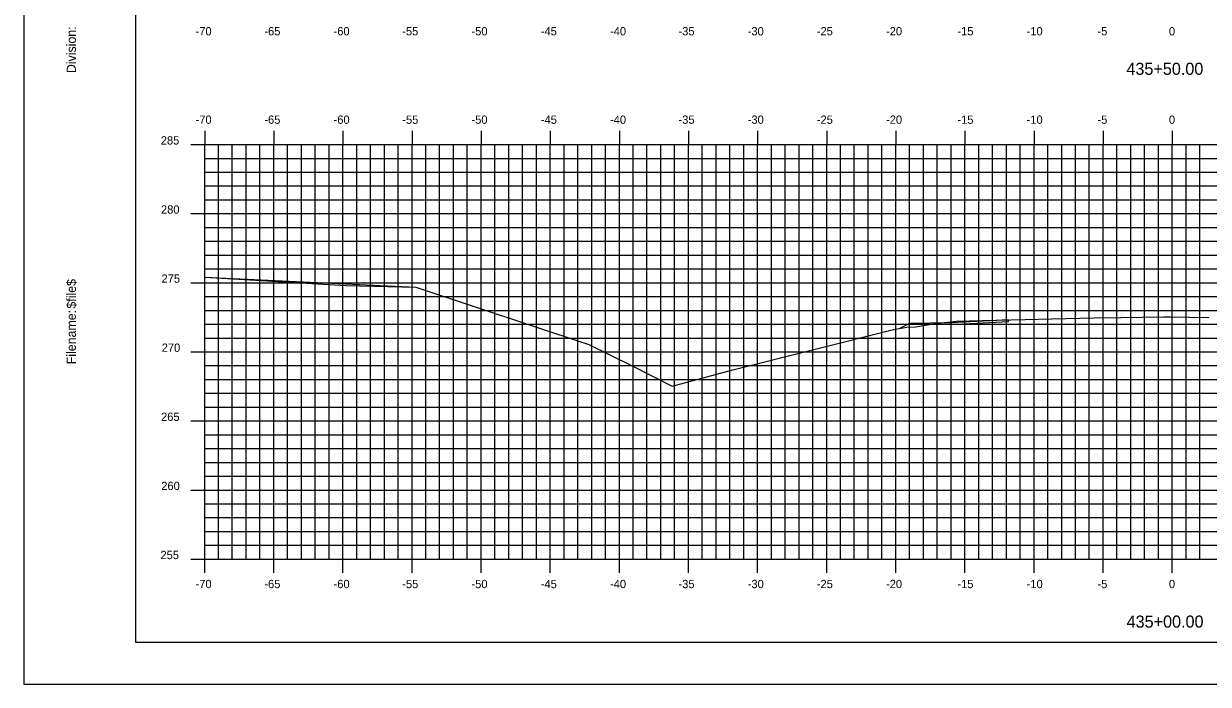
# Model space of a CAD drawing. Extents: x 1168600 to 1177589, y 610178 to 611246.
# Drawn here: x 1176654.6 to 1176740.3, y 610900.5 to 610948.3 of the extents above; entities that cross this region are included whole.
import ezdxf

# ---------------------------------------------------------------- set-up
doc = ezdxf.new("R2010")
doc.units = 0
for name, color, linetype in [('_Construction', 7, 'Continuous'), ('_Station Equation', 7, 'Continuous'), ('D_Roadway_Edge_TW', 7, 'Continuous'), ('D_Slope_Direction', 7, 'Continuous'), ('H_V ANNOTATION', 7, 'Continuous'), ('MAJOR', 7, 'Continuous'), ('MATCH LINES', 7, 'Continuous'), ('MINOR', 7, 'Continuous')]:
    doc.layers.add(name, color=color, linetype=linetype)

msp = doc.modelspace()

# ---------------------------------------------------------------- linework, layer by layer
at = {"layer": '_Construction'}
for points in [[(1176654.596, 610900.537), (1176824.596, 610900.537), (1176824.596, 611010.537), (1176654.596, 611010.537)], [(1176662.689, 610903.596), (1176822.689, 610903.596), (1176822.689, 611008.596), (1176662.689, 611008.596)]]:
    msp.add_lwpolyline(points, close=True, dxfattribs=at)
at = {"layer": '_Station Equation'}
for points in [[(1176667.689, 610929.994), (1176682.974, 610929.275), (1176695.478, 610925.138), (1176698.574, 610923.612), (1176701.51, 610922.119), (1176705.899, 610923.304), (1176717.518, 610926.22), (1176718.491, 610926.371), (1176719.109, 610926.405), (1176720.517, 610926.635), (1176721.211, 610926.723), (1176722.046, 610926.812), (1176723.965, 610926.861), (1176727.046, 610926.94), (1176728.963, 610926.98), (1176732.046, 610927.044), (1176733.961, 610927.076), (1176737.046, 610927.132), (1176737.349, 610927.134), (1176737.544, 610927.135), (1176740.331, 610927.075)], [(1176667.689, 610929.99), (1176677.908, 610929.4), (1176682.974, 610929.275), (1176695.479, 610925.138), (1176698.575, 610923.612), (1176701.51, 610922.119), (1176705.898, 610923.304), (1176717.518, 610926.22), (1176718.491, 610926.371), (1176719.109, 610926.405), (1176720.517, 610926.635), (1176721.211, 610926.723), (1176722.046, 610926.812), (1176723.966, 610926.861), (1176727.046, 610926.94), (1176728.964, 610926.98), (1176732.046, 610927.044), (1176733.962, 610927.076), (1176737.046, 610927.132), (1176737.349, 610927.134), (1176737.544, 610927.135), (1176740.33, 610927.075)]]:
    msp.add_lwpolyline(points, dxfattribs=at)
at = {"layer": 'D_Roadway_Edge_TW'}
msp.add_lwpolyline([(1176725.849, 610926.91), (1176721.69, 610926.694), (1176721.69, 610926.694), (1176721.69, 610926.569), (1176725.849, 610926.785), (1176725.849, 610926.91)], dxfattribs=at)
msp.add_lwpolyline([(1176725.849, 610926.91), (1176721.69, 610926.694), (1176721.69, 610926.694), (1176721.69, 610926.569), (1176725.849, 610926.785), (1176725.849, 610926.91)], dxfattribs=at)
at = {"layer": 'D_Slope_Direction'}
for points in [[(1176718.689, 610926.634), (1176718.016, 610926.297)], [(1176718.689, 610926.634), (1176718.016, 610926.297)], [(1176718.689, 610926.634), (1176718.016, 610926.297)], [(1176718.689, 610926.634), (1176718.016, 610926.297)], [(1176718.689, 610926.634), (1176718.016, 610926.297)], [(1176718.689, 610926.634), (1176718.016, 610926.297)], [(1176718.689, 610926.634), (1176718.016, 610926.297)], [(1176721.69, 610926.694), (1176718.689, 610926.634)], [(1176721.69, 610926.694), (1176718.689, 610926.634)]]:
    msp.add_lwpolyline(points, dxfattribs=at)
at = {"layer": 'MAJOR'}
for p, q in [((1176667.689, 610940.598), (1176667.689, 610939.596)), ((1176672.689, 610940.598), (1176672.689, 610939.596)), ((1176677.689, 610940.598), (1176677.689, 610939.596)), ((1176682.689, 610940.598), (1176682.689, 610939.596)), ((1176687.689, 610940.598), (1176687.689, 610939.596)), ((1176692.689, 610940.598), (1176692.689, 610939.596)), ((1176697.689, 610940.598), (1176697.689, 610939.596)), ((1176702.689, 610940.598), (1176702.689, 610939.596)), ((1176707.689, 610940.598), (1176707.689, 610939.596)), ((1176712.689, 610940.598), (1176712.689, 610939.596)), ((1176717.689, 610940.598), (1176717.689, 610939.596)), ((1176722.689, 610940.598), (1176722.689, 610939.596)), ((1176727.689, 610940.598), (1176727.689, 610939.596)), ((1176732.689, 610940.598), (1176732.689, 610939.596)), ((1176737.689, 610940.598), (1176737.689, 610939.596)), ((1176666.687, 610939.596), (1176667.689, 610939.596)), ((1176667.689, 610939.596), (1176807.689, 610939.596)), ((1176667.689, 610909.596), (1176667.689, 610939.596)), ((1176667.689, 610909.596), (1176667.689, 610939.596)), ((1176667.689, 610939.596), (1176807.689, 610939.596)), ((1176672.689, 610909.596), (1176672.689, 610939.596)), ((1176677.689, 610909.596), (1176677.689, 610939.596)), ((1176682.689, 610909.596), (1176682.689, 610939.596)), ((1176687.689, 610909.596), (1176687.689, 610939.596)), ((1176692.689, 610909.596), (1176692.689, 610939.596)), ((1176697.689, 610909.596), (1176697.689, 610939.596)), ((1176702.689, 610909.596), (1176702.689, 610939.596)), ((1176707.689, 610909.596), (1176707.689, 610939.596)), ((1176712.689, 610909.596), (1176712.689, 610939.596)), ((1176717.689, 610909.596), (1176717.689, 610939.596)), ((1176722.689, 610909.596), (1176722.689, 610939.596)), ((1176727.689, 610909.596), (1176727.689, 610939.596)), ((1176732.689, 610909.596), (1176732.689, 610939.596)), ((1176737.689, 610909.596), (1176737.689, 610939.596)), ((1176666.687, 610934.596), (1176667.689, 610934.596)), ((1176667.689, 610934.596), (1176807.689, 610934.596)), ((1176666.687, 610929.596), (1176667.689, 610929.596)), ((1176667.689, 610929.596), (1176807.689, 610929.596)), ((1176666.687, 610924.596), (1176667.689, 610924.596)), ((1176667.689, 610924.596), (1176807.689, 610924.596)), ((1176666.687, 610919.596), (1176667.689, 610919.596)), ((1176667.689, 610919.596), (1176807.689, 610919.596)), ((1176666.687, 610914.596), (1176667.689, 610914.596)), ((1176667.689, 610914.596), (1176807.689, 610914.596)), ((1176666.687, 610909.596), (1176667.689, 610909.596)), ((1176667.689, 610909.596), (1176807.689, 610909.596)), ((1176667.689, 610909.596), (1176807.689, 610909.596)), ((1176667.689, 610908.594), (1176667.689, 610909.596)), ((1176672.689, 610908.594), (1176672.689, 610909.596)), ((1176677.689, 610908.594), (1176677.689, 610909.596)), ((1176682.689, 610908.594), (1176682.689, 610909.596)), ((1176687.689, 610908.594), (1176687.689, 610909.596)), ((1176692.689, 610908.594), (1176692.689, 610909.596)), ((1176697.689, 610908.594), (1176697.689, 610909.596)), ((1176702.689, 610908.594), (1176702.689, 610909.596)), ((1176707.689, 610908.594), (1176707.689, 610909.596)), ((1176712.689, 610908.594), (1176712.689, 610909.596)), ((1176717.689, 610908.594), (1176717.689, 610909.596)), ((1176722.689, 610908.594), (1176722.689, 610909.596)), ((1176727.689, 610908.594), (1176727.689, 610909.596)), ((1176732.689, 610908.594), (1176732.689, 610909.596)), ((1176737.689, 610908.594), (1176737.689, 610909.596))]:
    msp.add_line(p, q, dxfattribs=at)
at = {"layer": 'MATCH LINES'}
msp.add_lwpolyline([(1176721.69, 610926.694), (1176721.69, 610926.569)], dxfattribs=at)
msp.add_lwpolyline([(1176721.69, 610926.694), (1176721.69, 610926.569)], dxfattribs=at)
at = {"layer": 'MINOR'}
for p, q in [((1176668.689, 610909.596), (1176668.689, 610939.596)), ((1176669.689, 610909.596), (1176669.689, 610939.596)), ((1176670.689, 610909.596), (1176670.689, 610939.596)), ((1176671.689, 610909.596), (1176671.689, 610939.596)), ((1176673.689, 610909.596), (1176673.689, 610939.596)), ((1176674.689, 610909.596), (1176674.689, 610939.596)), ((1176675.689, 610909.596), (1176675.689, 610939.596)), ((1176676.689, 610909.596), (1176676.689, 610939.596)), ((1176678.689, 610909.596), (1176678.689, 610939.596)), ((1176679.689, 610909.596), (1176679.689, 610939.596)), ((1176680.689, 610909.596), (1176680.689, 610939.596)), ((1176681.689, 610909.596), (1176681.689, 610939.596)), ((1176683.689, 610909.596), (1176683.689, 610939.596)), ((1176684.689, 610909.596), (1176684.689, 610939.596)), ((1176685.689, 610909.596), (1176685.689, 610939.596)), ((1176686.689, 610909.596), (1176686.689, 610939.596)), ((1176688.689, 610909.596), (1176688.689, 610939.596)), ((1176689.689, 610909.596), (1176689.689, 610939.596)), ((1176690.689, 610909.596), (1176690.689, 610939.596)), ((1176691.689, 610909.596), (1176691.689, 610939.596)), ((1176693.689, 610909.596), (1176693.689, 610939.596)), ((1176694.689, 610909.596), (1176694.689, 610939.596)), ((1176695.689, 610909.596), (1176695.689, 610939.596)), ((1176696.689, 610909.596), (1176696.689, 610939.596)), ((1176698.689, 610909.596), (1176698.689, 610939.596)), ((1176699.689, 610909.596), (1176699.689, 610939.596)), ((1176700.689, 610909.596), (1176700.689, 610939.596)), ((1176701.689, 610909.596), (1176701.689, 610939.596)), ((1176703.689, 610909.596), (1176703.689, 610939.596)), ((1176704.689, 610909.596), (1176704.689, 610939.596)), ((1176705.689, 610909.596), (1176705.689, 610939.596)), ((1176706.689, 610909.596), (1176706.689, 610939.596)), ((1176708.689, 610909.596), (1176708.689, 610939.596)), ((1176709.689, 610909.596), (1176709.689, 610939.596)), ((1176710.689, 610909.596), (1176710.689, 610939.596)), ((1176711.689, 610909.596), (1176711.689, 610939.596)), ((1176713.689, 610909.596), (1176713.689, 610939.596)), ((1176714.689, 610909.596), (1176714.689, 610939.596)), ((1176715.689, 610909.596), (1176715.689, 610939.596)), ((1176716.689, 610909.596), (1176716.689, 610939.596)), ((1176718.689, 610909.596), (1176718.689, 610939.596)), ((1176719.689, 610909.596), (1176719.689, 610939.596)), ((1176720.689, 610909.596), (1176720.689, 610939.596)), ((1176721.689, 610909.596), (1176721.689, 610939.596)), ((1176723.689, 610909.596), (1176723.689, 610939.596)), ((1176724.689, 610909.596), (1176724.689, 610939.596)), ((1176725.689, 610909.596), (1176725.689, 610939.596)), ((1176726.689, 610909.596), (1176726.689, 610939.596)), ((1176728.689, 610909.596), (1176728.689, 610939.596)), ((1176729.689, 610909.596), (1176729.689, 610939.596)), ((1176730.689, 610909.596), (1176730.689, 610939.596)), ((1176731.689, 610909.596), (1176731.689, 610939.596)), ((1176733.689, 610909.596), (1176733.689, 610939.596)), ((1176734.689, 610909.596), (1176734.689, 610939.596)), ((1176735.689, 610909.596), (1176735.689, 610939.596)), ((1176736.689, 610909.596), (1176736.689, 610939.596)), ((1176738.689, 610909.596), (1176738.689, 610939.596)), ((1176739.689, 610909.596), (1176739.689, 610939.596)), ((1176667.689, 610938.596), (1176807.689, 610938.596)), ((1176667.689, 610938.596), (1176668.691, 610938.596)), ((1176667.689, 610937.596), (1176807.689, 610937.596)), ((1176667.689, 610937.596), (1176668.691, 610937.596)), ((1176667.689, 610936.596), (1176807.689, 610936.596)), ((1176667.689, 610936.596), (1176668.691, 610936.596)), ((1176667.689, 610935.596), (1176807.689, 610935.596)), ((1176667.689, 610935.596), (1176668.691, 610935.596)), ((1176667.689, 610933.596), (1176807.689, 610933.596)), ((1176667.689, 610933.596), (1176668.691, 610933.596)), ((1176667.689, 610932.596), (1176807.689, 610932.596)), ((1176667.689, 610932.596), (1176668.691, 610932.596)), ((1176667.689, 610931.596), (1176807.689, 610931.596)), ((1176667.689, 610931.596), (1176668.691, 610931.596)), ((1176667.689, 610930.596), (1176807.689, 610930.596)), ((1176667.689, 610930.596), (1176668.691, 610930.596)), ((1176667.689, 610928.596), (1176807.689, 610928.596)), ((1176667.689, 610928.596), (1176668.691, 610928.596)), ((1176667.689, 610927.596), (1176807.689, 610927.596)), ((1176667.689, 610927.596), (1176668.691, 610927.596)), ((1176667.689, 610926.596), (1176807.689, 610926.596)), ((1176667.689, 610926.596), (1176668.691, 610926.596)), ((1176667.689, 610925.596), (1176807.689, 610925.596)), ((1176667.689, 610925.596), (1176668.691, 610925.596)), ((1176667.689, 610923.596), (1176807.689, 610923.596)), ((1176667.689, 610923.596), (1176668.691, 610923.596)), ((1176667.689, 610922.596), (1176807.689, 610922.596)), ((1176667.689, 610922.596), (1176668.691, 610922.596)), ((1176667.689, 610921.596), (1176807.689, 610921.596)), ((1176667.689, 610921.596), (1176668.691, 610921.596)), ((1176667.689, 610920.596), (1176807.689, 610920.596)), ((1176667.689, 610920.596), (1176668.691, 610920.596)), ((1176667.689, 610918.596), (1176807.689, 610918.596)), ((1176667.689, 610918.596), (1176668.691, 610918.596)), ((1176667.689, 610917.596), (1176807.689, 610917.596)), ((1176667.689, 610917.596), (1176668.691, 610917.596)), ((1176667.689, 610916.596), (1176807.689, 610916.596)), ((1176667.689, 610916.596), (1176668.691, 610916.596)), ((1176667.689, 610915.596), (1176807.689, 610915.596)), ((1176667.689, 610915.596), (1176668.691, 610915.596)), ((1176667.689, 610913.596), (1176807.689, 610913.596)), ((1176667.689, 610913.596), (1176668.691, 610913.596)), ((1176667.689, 610912.596), (1176807.689, 610912.596)), ((1176667.689, 610912.596), (1176668.691, 610912.596)), ((1176667.689, 610911.596), (1176807.689, 610911.596)), ((1176667.689, 610911.596), (1176668.691, 610911.596)), ((1176667.689, 610910.596), (1176807.689, 610910.596)), ((1176667.689, 610910.596), (1176668.691, 610910.596))]:
    msp.add_line(p, q, dxfattribs=at)

# ---------------------------------------------------------------- texts
at = {"layer": '_Construction'}
for s, p in [('Division:', (1176658.374, 610944.762)), ('$file$', (1176658.374, 610927.722)), ('Filename:', (1176658.374, 610923.695))]:
    msp.add_text(s, height=0.6696, rotation=90, dxfattribs=at).set_placement(p)
at = {"layer": 'H_V ANNOTATION'}
for s, height, p in [('-70', 0.6, (1176667.031, 610947.496)), ('-65', 0.6, (1176672.007, 610947.496)), ('-60', 0.6, (1176677.015, 610947.496)), ('-55', 0.6, (1176681.985, 610947.496)), ('-50', 0.6, (1176686.993, 610947.496)), ('-45', 0.6, (1176692.007, 610947.496)), ('-40', 0.6, (1176697.015, 610947.496)), ('-35', 0.6, (1176701.969, 610947.496)), ('-30', 0.6, (1176706.977, 610947.496)), ('-25', 0.6, (1176711.975, 610947.496)), ('-20', 0.6, (1176716.983, 610947.496)), ('-15', 0.6, (1176722.146, 610947.496)), ('-10', 0.6, (1176727.154, 610947.496)), ('-5', 0.6, (1176732.28, 610947.496)), ('0', 0.6, (1176737.448, 610947.496)), ('435+50.00', 0.875, (1176734.373, 610944.639)), ('-70', 0.6, (1176667.031, 610941.096)), ('-65', 0.6, (1176672.007, 610941.096)), ('-60', 0.6, (1176677.015, 610941.096)), ('-55', 0.6, (1176681.985, 610941.096)), ('-50', 0.6, (1176686.993, 610941.096)), ('-45', 0.6, (1176692.007, 610941.096)), ('-40', 0.6, (1176697.015, 610941.096)), ('-35', 0.6, (1176701.969, 610941.096)), ('-30', 0.6, (1176706.977, 610941.096)), ('-25', 0.6, (1176711.975, 610941.096)), ('-20', 0.6, (1176716.983, 610941.096)), ('-15', 0.6, (1176722.146, 610941.096)), ('-10', 0.6, (1176727.154, 610941.096)), ('-5', 0.6, (1176732.28, 610941.096)), ('0', 0.6, (1176737.448, 610941.096)), ('285', 0.6, (1176664.514, 610939.596)), ('280', 0.6, (1176664.53, 610934.596)), ('275', 0.6, (1176664.567, 610929.596)), ('270', 0.6, (1176664.583, 610924.596)), ('265', 0.6, (1176664.535, 610919.596)), ('260', 0.6, (1176664.551, 610914.596)), ('255', 0.6, (1176664.492, 610909.596)), ('-70', 0.6, (1176667.031, 610907.496)), ('-65', 0.6, (1176672.007, 610907.496)), ('-60', 0.6, (1176677.015, 610907.496)), ('-55', 0.6, (1176681.985, 610907.496)), ('-50', 0.6, (1176686.993, 610907.496)), ('-45', 0.6, (1176692.007, 610907.496)), ('-40', 0.6, (1176697.015, 610907.496)), ('-35', 0.6, (1176701.969, 610907.496)), ('-30', 0.6, (1176706.977, 610907.496)), ('-25', 0.6, (1176711.975, 610907.496)), ('-20', 0.6, (1176716.983, 610907.496)), ('-15', 0.6, (1176722.146, 610907.496)), ('-10', 0.6, (1176727.154, 610907.496)), ('-5', 0.6, (1176732.28, 610907.496)), ('0', 0.6, (1176737.448, 610907.496)), ('435+00.00', 0.875, (1176734.388, 610904.639))]:
    msp.add_text(s, height=height, dxfattribs=at).set_placement(p)

doc.saveas('drawing.dxf')
